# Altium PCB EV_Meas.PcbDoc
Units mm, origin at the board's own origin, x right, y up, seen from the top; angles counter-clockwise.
Board outline 85 x 150 mm, 2 copper layers (Top Layer, Bottom Layer); 79 components, 48 nets, 278 pads, 76 vias.
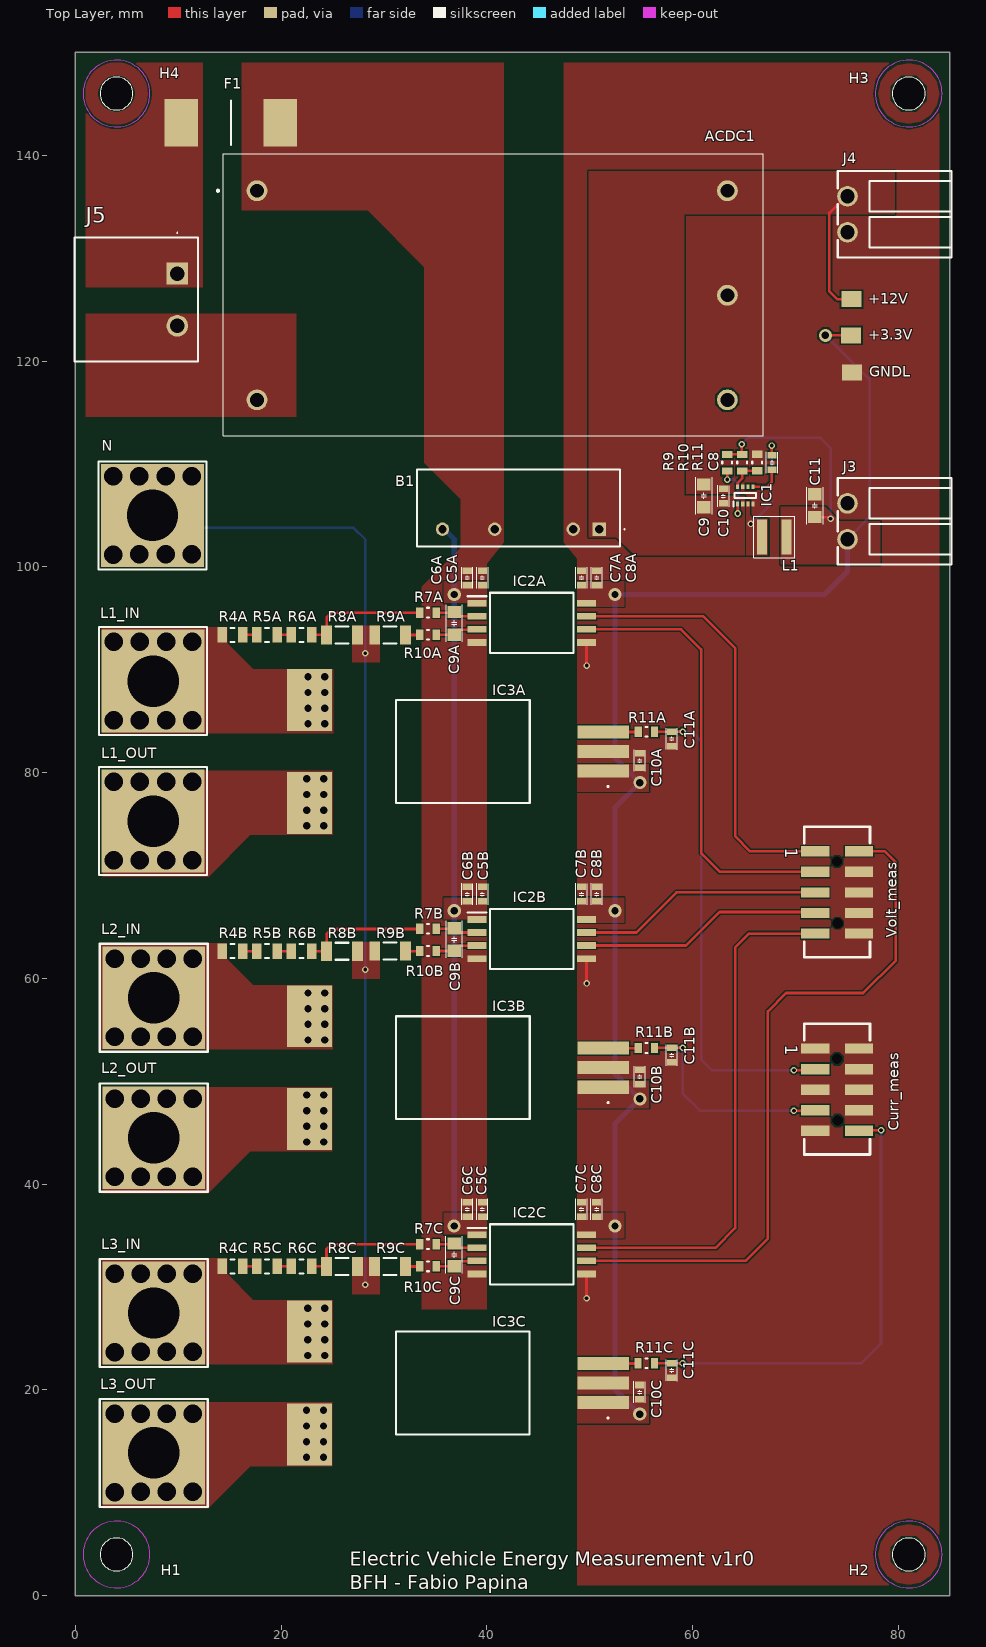
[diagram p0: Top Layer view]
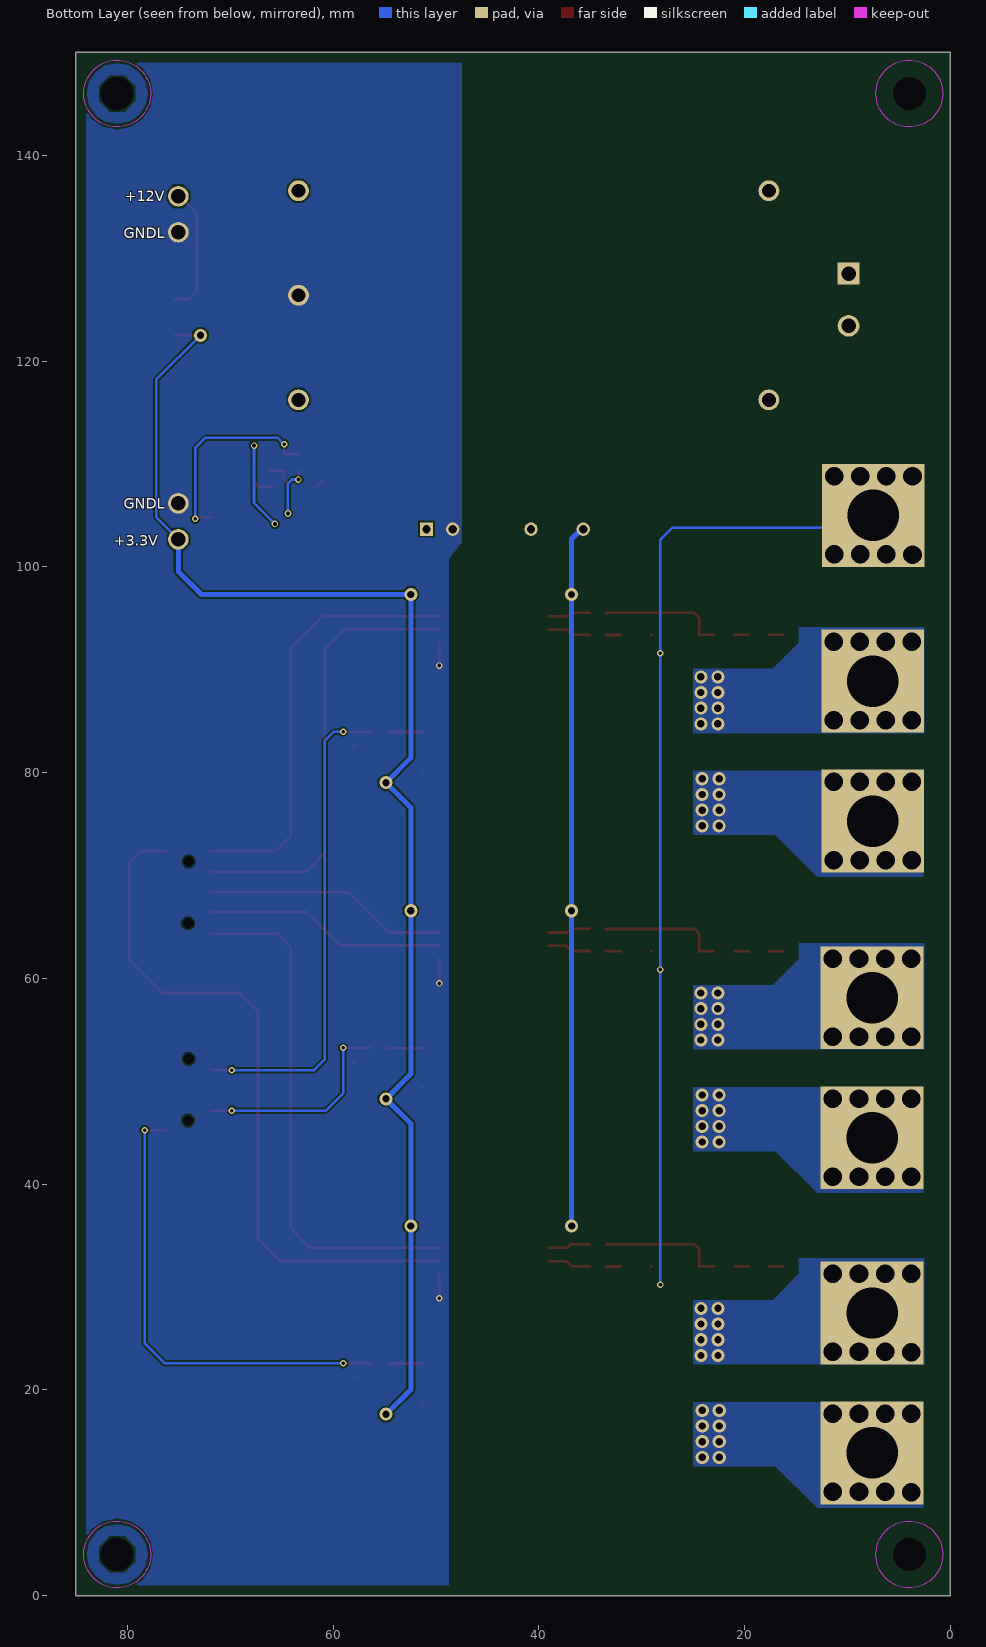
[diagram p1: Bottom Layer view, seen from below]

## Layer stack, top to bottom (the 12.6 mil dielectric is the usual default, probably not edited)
Top Solder: solder mask 0.0102, Solder Resist, Dk 3.5
Top Layer: signal copper 0.0356
Dielectric 1: dielectric 0.32, FR-4, Dk 4.8
Bottom Layer: signal copper 0.0356
Bottom Solder: solder mask 0.0102, Solder Resist, Dk 3.5

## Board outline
0,0 0,150 85,150 85,0

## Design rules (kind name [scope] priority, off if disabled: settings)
BoardOutlineClearance [All] p1: gap=1 ignorepadtopadclearanceinfootprint=FALSE
Clearance Clearance_multiCB [All] p1: gap=0.15 ignorepadtopadclearanceinfootprint=FALSE
Clearance [All] p2: gap=0.254 ignorepadtopadclearanceinfootprint=FALSE
Creepage [InNetClass('Isolated') vs InNetClass('Power')] p1: checkdistance=7
Height [All] p1: minheight=0 maxheight=60 prefheight=12.7
HoleSize HoleSize_multiCB [All] p1: absolutevalues=TRUE maxlimit=10 minlimit=0.2 maxpercent=80.000 minpercent=20.000
HoleSize [All] p2: absolutevalues=TRUE maxlimit=2.54 minlimit=0.025 maxpercent=80.000 minpercent=20.000
MinimumAnnularRing MinimumAnnularRing_multiCB [All] p1: minimumring=0.1
MinimumSolderMaskSliver MinimumSolderMaskSliver_multiCB [All] p1: minsoldermaskwidth=0.1
MinimumSolderMaskSliver [All] p2: minsoldermaskwidth=0.254
PlaneConnect [All] p1: planeconnectstyle=Direct reliefexpansion=0.508 reliefentries=4 reliefconductorwidth=0.254 reliefairgap=0.254
PolygonConnect PolygonConnect_Power [InNetClass('Power')] p1: connectstyle=Direct reliefconductorwidth=0.254 reliefentries=4 polygonreliefangle="90 Angle" airgapwidth=0.254
PolygonConnect [All] p2: connectstyle=Direct reliefconductorwidth=0.254 reliefentries=4 polygonreliefangle="90 Angle" airgapwidth=0.254
RoutingVias RoutingVias_multiCB [All] p1: holewidth=0.2 width=0.4 viastyle="Through Hole" minholewidth=0.2 minwidth=0.4 maxholewidth=0.2 maxwidth=0.4
RoutingVias [All] p2: holewidth=0.711 width=1.27 viastyle="Through Hole" minholewidth=0.711 minwidth=1.27 maxholewidth=0.711 maxwidth=1.27
SilkToSilkClearance SilkToSilkClearance_multiCB [All] p1: silktosilkclearance=0.1
SilkToSilkClearance [All] p2: silktosilkclearance=0.254
SilkToSolderMaskClearance SilkToSolderMaskClearance_multiCB [IsPad] p1: minsilkscreentomaskgap=0.15 clearancetoexposedcopper=TRUE
SilkToSolderMaskClearance [IsPad] p2: minsilkscreentomaskgap=0.254 clearancetoexposedcopper=TRUE
SolderMaskExpansion [All] p1: expansion=0.102 istentingtop=FALSE
Width High_current [InNetClass('High_Current')] p1: maxlimit=4.318 minlimit=0.254 preferedwidth=4.318 minimp=50.000000 maximp=50.000000 favimp=50.000000
Width Width_multiCB [All] p2: maxlimit=0.5 minlimit=0.254 preferedwidth=0.254
24 further rules are at their usual default settings.

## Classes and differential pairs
channel class Phase_Meas: U_Phase_Meas1 U_Phase_Meas2 U_Phase_Meas3
component class U_Phase_Meas3: C5C C6C C7C C8C C9C C10C C11C IC2C IC3C R4C R5C R6C R7C R8C R9C R10C R11C
component class U_Phase_Meas2: C5B C6B C7B C8B C9B C10B C11B IC2B IC3B R4B R5B R6B R7B R8B R9B R10B R11B
component class U_Phase_Meas1: C5A C6A C7A C8A C9A C10A C11A IC2A IC3A R4A R5A R6A R7A R8A R9A R10A R11A
component class TopSchematic: Curr_meas H1 H2 H3 H4 J3 J4 J5 L1_IN L1_OUT L2_IN L2_OUT L3_IN L3_OUT M1 M2 M3 M4 M5 M6 M7 M8 Meas_iso1 Meas_iso2 N Volt_meas
component class U_Power_supplies: ACDC1 B1 C8 C9 C10 C11 F1 IC1 L1 R9 R10 R11

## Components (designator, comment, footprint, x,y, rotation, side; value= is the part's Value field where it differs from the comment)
ACDC1 "RAC10-12SK_277" RAC1005SK277 17.653,136.548 r0 top
B1 "MDS01M-05N" MDS01M05N 50.927,103.655 r180 top
C5A "C-SMD-0603" C-0603 39.565,98.924 r270 top value=1uF (schematic designator C5)
C5B "C-SMD-0603" C-0603 39.565,68.19 r270 top value=1uF (schematic designator C5)
C5C "C-SMD-0603" C-0603 39.559,37.54 r270 top value=1uF (schematic designator C5)
C6A "C-SMD-0603" C-0603 38.091,98.924 r270 top value=0.1uF (schematic designator C6)
C6B "C-SMD-0603" C-0603 38.091,68.19 r270 top value=0.1uF (schematic designator C6)
C6C "C-SMD-0603" C-0603 38.085,37.54 r270 top value=0.1uF (schematic designator C6)
C7A "C-SMD-0603" C-0603 49.198,98.924 r270 top value=1uF (schematic designator C7)
C7B "C-SMD-0603" C-0603 49.198,68.19 r270 top value=1uF (schematic designator C7)
C7C "C-SMD-0603" C-0603 49.192,37.54 r270 top value=1uF (schematic designator C7)
C8 "C-SMD-0603" C-0603 67.725,110.132 r270 top value=0.1uF
C8A "C-SMD-0603" C-0603 50.674,98.924 r270 top value=0.1uF (schematic designator C8)
C8B "C-SMD-0603" C-0603 50.674,68.19 r270 top value=0.1uF (schematic designator C8)
C8C "C-SMD-0603" C-0603 50.668,37.54 r270 top value=0.1uF (schematic designator C8)
C9 "C-SMD-0805" C-0805 61.096,106.893 r270 top value=22uF
C9A "C-SMD-0805" C-0805 36.83,94.511 r90 top value=330pF (schematic designator C9)
C9B "C-SMD-0805" C-0805 36.83,63.777 r90 top value=330pF (schematic designator C9)
C9C "C-SMD-0805" C-0805 36.824,33.127 r90 top value=330pF (schematic designator C9)
C10 "C-SMD-0603" C-0603 62.993,106.868 r270 top value=0.1uF
C10A "C-SMD-0603" C-0603 54.853,81.158 r270 top value=0.1uF (schematic designator C10)
C10B "C-SMD-0603" C-0603 54.853,50.424 r270 top value=0.1uF (schematic designator C10)
C10C "C-SMD-0603" C-0603 54.847,19.774 r270 top value=0.1uF (schematic designator C10)
C11 "C-SMD-0805" C-0805 71.882,105.941 r270 top value=22uF
C11A "C-SMD-0603" C-0603 57.971,83.27 r90 top value=680nF (schematic designator C11)
C11B "C-SMD-0603" C-0603 57.971,52.536 r90 top value=680nF (schematic designator C11)
C11C "C-SMD-0603" C-0603 57.965,21.886 r90 top value=680nF (schematic designator C11)
Curr_meas "Molex MILLI-GRID SMD 5x2 2mm 87832-1020" 87832-1020r 74.041,49.172 r270 top
F1 "0465002.DR" FUSC12145X450N 15.113,143.152 r0 top
H1 "3.2" HOLE_3.2_NP 4,4 r0 top
H2 "3.2" HOLE_3.2_NP 81,4 r0 top
H3 "3.2" HOLE_3.2_NP 81,146 r0 top
H4 "3.2" HOLE_3.2_NP 4,146 r0 top
IC1 "TPS562211DRLR" SOTFL50P160X60-8N 65.123,106.938 r90 top
IC2A "AMC1300BDWV" SOIC127P1150X280-8N 44.361,94.555 r0 top (schematic designator IC2)
IC2B "AMC1300BDWV" SOIC127P1150X280-8N 44.361,63.821 r0 top (schematic designator IC2)
IC2C "AMC1300BDWV" SOIC127P1150X280-8N 44.355,33.17 r0 top (schematic designator IC2)
IC3A "ACS773KCB-150B-SMT-T" ACS772LCB050BSMTT 37.665,82.046 r90 top (schematic designator IC3)
IC3B "ACS773KCB-150B-SMT-T" ACS772LCB050BSMTT 37.665,51.312 r90 top (schematic designator IC3)
IC3C "ACS773KCB-150B-SMT-T" ACS772LCB050BSMTT 37.659,20.662 r90 top (schematic designator IC3)
J3 "Weidmuller_3.5 2X1" SL_3_50_90G_02 79.629,104.417 r90 top
J4 "Weidmuller_3.5 2X1" SL_3_50_90G_02 79.629,134.262 r90 top
J5 "1821140000" 1821140000 9.906,128.502 r270 top
L1 "XAL4030-472MEC" XAL4030472MEC 67.945,102.893 r0 top
L1_IN "Borne_4mm" Borne4mm_WE 7.553,88.881 r0 top
L1_OUT "Borne_4mm" Borne4mm_WE 7.553,75.275 r0 top
L2_IN "Borne_4mm" Borne4mm_WE 7.62,58.113 r0 top
L2_OUT "Borne_4mm" Borne4mm_WE 7.62,44.507 r0 top
L3_IN "Borne_4mm" Borne4mm_WE 7.62,27.472 r0 top
L3_OUT "Borne_4mm" Borne4mm_WE 7.62,13.866 r0 top
N "Borne_4mm" Borne4mm_WE 7.5,105 r0 top
R4A "R-SMD-0805" R-0805 15.285,93.383 r0 top value=2.2Meg (schematic designator R4)
R4B "R-SMD-0805" R-0805 15.285,62.649 r0 top value=2.2Meg (schematic designator R4)
R4C "R-SMD-0805" R-0805 15.279,31.999 r0 top value=2.2Meg (schematic designator R4)
R5A "R-SMD-0805" R-0805 18.642,93.383 r0 top value=2.2Meg (schematic designator R5)
R5B "R-SMD-0805" R-0805 18.642,62.649 r0 top value=2.2Meg (schematic designator R5)
R5C "R-SMD-0805" R-0805 18.636,31.999 r0 top value=2.2Meg (schematic designator R5)
R6A "R-SMD-0805" R-0805 22,93.383 r0 top value=2.2Meg (schematic designator R6)
R6B "R-SMD-0805" R-0805 22,62.649 r0 top value=2.2Meg (schematic designator R6)
R6C "R-SMD-0805" R-0805 21.994,31.999 r0 top value=2.2Meg (schematic designator R6)
R7A "R-SMD-0603" R-0603 34.29,95.527 r0 top value=12 (schematic designator R7)
R7B "R-SMD-0603" R-0603 34.29,64.793 r0 top value=12 (schematic designator R7)
R7C "R-SMD-0603" R-0603 34.284,34.143 r0 top value=12 (schematic designator R7)
R8A "R-SMD-1206" R-1206 25.908,93.368 r180 top value=5.62k (schematic designator R8)
R8B "R-SMD-1206" R-1206 25.908,62.634 r180 top value=5.62k (schematic designator R8)
R8C "R-SMD-1206" R-1206 25.902,31.984 r180 top value=5.62k (schematic designator R8)
R9 "R-SMD-0603" R-0603 63.373,110.132 r90 top value=10k
R9A "R-SMD-1206" R-1206 30.607,93.368 r0 top value=5.62k (schematic designator R9)
R9B "R-SMD-1206" R-1206 30.607,62.634 r0 top value=5.62k (schematic designator R9)
R9C "R-SMD-1206" R-1206 30.601,31.984 r0 top value=5.62k (schematic designator R9)
R10 "R-SMD-0603" R-0603 64.83,110.132 r90 top value=45.3k
R10A "R-SMD-0603" R-0603 34.29,93.368 r0 top value=12 (schematic designator R10)
R10B "R-SMD-0603" R-0603 34.29,62.634 r0 top value=12 (schematic designator R10)
R10C "R-SMD-0603" R-0603 34.284,31.984 r0 top value=12 (schematic designator R10)
R11 "R-SMD-0603" R-0603 66.25,110.132 r270 top value=10k
R11A "R-SMD-0603" R-0603 55.513,83.949 r0 top value=12 (schematic designator R11)
R11B "R-SMD-0603" R-0603 55.513,53.215 r0 top value=12 (schematic designator R11)
R11C "R-SMD-0603" R-0603 55.507,22.564 r0 top value=12 (schematic designator R11)
Volt_meas "Molex MILLI-GRID SMD 5x2 2mm 87832-1020" 87832-1020r 74.041,68.349 r270 top

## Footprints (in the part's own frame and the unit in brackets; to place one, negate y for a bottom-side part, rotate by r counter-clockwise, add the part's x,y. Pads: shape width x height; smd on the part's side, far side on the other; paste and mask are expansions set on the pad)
87832-1020r [mm]
  round 0 hole 1 unplated mask+0: 0(-3,0) 0(3,0.051)
  rect 1x2.75 smd: 1(-4,-2.125) 2(-4,2.125) 3(-2,-2.125) 4(-2,2.125) 5(0,-2.125) 6(0,2.125) 7(2,-2.125) 8(2,2.125) 9(4,-2.125) 10(4,2.125)
  silkscreen extent -6.4,-3.2 6.3,3.2, body extent -8.32,-3.15 8.33,3.15, height 15.15
1821140000 [mm]
  rect 2.1x2.1 hole 1.4: 1(0,0)
  round 2.1 hole 1.4: 2(5.08,0)
  silkscreen extent -4,-10 8.57,2, body extent -3.49,-10 8.57,2, height 8.21
ACS772LCB050BSMTT [mm]
  rect 1.27x5.03 smd: 1(-1.9,-13.655) 2(0,-13.655) 3(1.9,-13.655)
  rect 6.01x4.4 smd: 4(4.995,14.9) 5(-4.995,14.9)
  silkscreen extent -4.99,-14.17 5,6.5, body extent -7,-14.83 7,14.82, height 7.5
Borne4mm_WE [mm]
  rect 2x2 hole 1.8: 1(-3.81,-3.81) 1(-3.81,3.81) 1(-1.27,-3.785) 1(-1.27,3.81) 1(1.27,-3.785) 1(1.27,3.81) 1(3.81,-3.785) 1(3.81,3.81)
  round 6 hole 5: 1(0,0)
  rect 10x10 smd far side paste-5: 1(0,0)
  rect 10x10 smd paste-5: 1(0,0)
  silkscreen extent -5.25,-5.25 5.25,5.25, body extent -4.5,-4.5 4.5,4.5, height 7
C-0603 [mm]
  rect 0.64x0.89 smd mask+0.05: 1(-0.7,0) 2(0.7,0)
  silkscreen extent -1.05,-0.55 1.02,0.55, body extent -0.9,-0.5 0.9,0.5, height 1.4
C-0805 [mm]
  rect 1.2x1.3 smd: 1(-1.1,0) 2(1.1,0)
  silkscreen extent -1.8,-0.8 1.8,0.8, body extent -1,-0.62 1,0.63, height 0.6
FUSC12145X450N [mm]
  rect 3.26x4.61 smd: 1(-4.825,0) 2(4.825,0)
  silkscreen extent 0,-2.15 0,2.15, body extent -6.05,-2.25 6.05,2.25, height 4.5
HOLE_3.2_NP [mm] "Hole non plated"
  round 0 hole 3.2 unplated: 0(0,0)
  Keep-Out Layer circle w0.1: c0,0 r3.25
  silkscreen extent -1.6,-1.6 1.6,1.6
MDS01M05N [mm]
  rect 1.3x1.3 hole 0.8: 1(0,0)
  round 1.3 hole 0.8: 2(2.54,0) 5(10.16,0) 7(15.24,0)
  silkscreen extent -2.5,-5.8 17.7,1.7, body extent -2,-5.8 17.7,1.7, height 12.1
R-0603 [mm]
  rect 0.7x1 smd: 1(-0.809,0.019) 2(0.791,0.019)
  silkscreen extent -0.11,-0.46 0.09,0.49, body extent -0.88,-0.46 0.87,0.49, height 0.54
R-0805 [mm]
  rect 0.9x1.5 smd: 1(-1.009,0) 2(0.991,0)
  silkscreen extent -0.21,-0.68 0.19,0.68, body extent -1.11,-0.67 1.09,0.68, height 0.69
R-1206 [mm]
  rect 1.05x1.85 smd: 1(-1.515,0.003) 2(1.485,0.003)
  silkscreen extent -0.64,-0.82 0.61,0.83, body extent -1.64,-0.82 1.61,0.83, height 0.69
RAC1005SK277 [mm]
  round 2.025 hole 1.35: 1(0,0) 2(0,-20.32) 3(45.72,-20.32) 4(45.72,-10.16) 5(45.72,0)
  silkscreen extent -3.9,-23.82 49.2,3.58, body extent -3.26,-23.73 49.24,3.67, height 23.01
SL_3_50_90G_02 [mm]
  round 2 hole 1.4: A1(-1.75,4.58) A2(1.75,4.58)
  silkscreen extent -4.2,-5.53 4.2,5.53, body extent -4.2,-5.52 4.2,5.53, height 7.46
SOIC127P1150X280-8N [mm]
  rect 1.85x0.65 smd: 1(-5.325,1.905) 2(-5.325,0.635) 3(-5.325,-0.635) 4(-5.325,-1.905) 5(5.325,-1.905) 6(5.325,-0.635) 7(5.325,0.635) 8(5.325,1.905)
  silkscreen extent -6.25,-2.93 4.05,2.93, body extent -5.77,-2.93 5.77,2.93, height 2.7
SOTFL50P160X60-8N [mm]
  rect 0.475x0.3 smd: 1(-0.838,0.75) 2(-0.838,0.25) 3(-0.838,-0.25) 4(-0.838,-0.75) 5(0.838,-0.75) 6(0.838,-0.25) 7(0.838,0.25) 8(0.838,0.75)
  silkscreen extent -1.07,-1.05 0.25,1.15, body extent -0.8,-1.05 0.8,1.05, height 0.6
XAL4030472MEC [mm]
  rect 0.98x3.4 smd: 1(-1.185,0) 2(1.185,0)
  silkscreen extent -2,-2 2,2, body extent -2,-2 2,2, height 3.1

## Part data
ACDC1: "Power Supply", Arrow Part Number=RAC10-12SK/277, Manufacturer_Name="RECOM Power", Mouser Part Number=919-RAC10-12SK/277
B1: "Isolated DC/DC Converters - Through Hole 1W 12Vin 5Vout 20-200mA SIP7 Medical Unregulated", Manufacturer_Name="Mean Well"
C5A C5B C5C C6A C6B C6C C7A C7B C7C C8 C8A C8B C8C C10 C10A C10B C10C C11A C11B C11C: library part CMP-003-000008-1, "Multilayer Ceramic Capacitors MLCC", Manufacturer="Murata Electronics", Mfr. Part No.=GRM18..., Package=0603
C9 C11: library part CMP-001-00107-1, "Multilayer Ceramic Capacitors MLCC", Case/Package=0805, Manufacturer="Murata Electronics", Mfr. Part No.=GRM21*
C9A C9B C9C: library part CMP-003-000005-1, "Multilayer Ceramic Capacitors MLCC", Manufacturer="Murata Electronics", Mfr. Part No.=GRM21*, Package=0805
Curr_meas Volt_meas: "87832-1020 -  Connecteur fil-à-carte, 2 mm, 10 Contact(s), Embase, Milli-Grid 87832 Series, Montage CMS", Colour=Black, Manufacturer=Molex, Manufacturer P/N=87832-1020, Manufacturer Part Number=0878321014, Max Operating Temperature=105°C, Min Operating Temperature=-55°C, Package Quantity=500, Supplier Part Number 1=WM14376TR-ND
F1: "Fuse", Manufacturer_Name=LITTELFUSE, Mouser Part Number=576-0465002.DR
H1 H2 H3 H4: library part HOLE_3.2_NP, "Hole 3.2 unplated"
IC1: "Integrated Circuit", Manufacturer_Name="Texas Instruments", Mouser Part Number=595-TPS562211DRLR
IC2A IC2B IC2C: "Integrated Circuit", Manufacturer_Name="Texas Instruments", Mouser Part Number=595-AMC1300BDWV
IC3A IC3B IC3C: "Integrated Circuit", Manufacturer_Name="Allegro Microsystems", Mouser Part Number=250-773KCB150BSMTT
J3 J4: "Series BL/SL 3.50 2-Pin", Manufacturer=Weidmuller, Manufacturer P/N="SL 3.50/02/90G"
J5: "Connector", Manufacturer_Name=Weidmuller, Mouser Part Number=470-1821140000
L1: "Inductor", Manufacturer_Name=COILCRAFT, Mouser Part Number=994-XAL4030-472MEC
L1_IN L1_OUT L2_IN L2_OUT L3_IN L3_OUT N: library part Borne_4mm_WE, "Borne 4mm avec connecteur WE", Manufacturer=WE, Manufacturer P/N=7460305
R4A R4B R4C R5A R5B R5C R6A R6B R6C: library part CMP-013-000007-1, "Thin Film Resistors - SMD  0.1W  1%", Manufacturer="Vishay / Beyschlag", Mfr. Part No.=MCT06030C*, Package=0805
R7A R7B R7C R9 R10 R10A R10B R10C R11 R11A R11B R11C: library part CMP-013-000006-1, "Thin Film Resistors - SMD  0.1W  1%", Manufacturer="Vishay / Beyschlag", Mfr. Part No.=MCU08050C*, Package=0603
R8A R8B R8C R9A R9B R9C: library part CMP-013-000008-1, "Thin Film Resistors - SMD  0.1W  1%", Manufacturer="Vishay / Beyschlag", Mfr. Part No.=MCA12060C, Package=1206

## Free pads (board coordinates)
  rect 1.95x1.55 smd: TP(75.4,122.5) TP(75.438,126.007) TP(75.5,118.9)

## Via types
v1: diameter 1.27, hole 0.711, Top Layer to Bottom Layer, 58 vias
v2: diameter 0.635, hole 0.356, Top Layer to Bottom Layer, 18 vias

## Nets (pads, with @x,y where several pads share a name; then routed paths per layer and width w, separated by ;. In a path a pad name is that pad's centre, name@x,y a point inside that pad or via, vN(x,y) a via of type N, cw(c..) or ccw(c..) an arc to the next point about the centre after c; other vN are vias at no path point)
GND5: ACDC1.1 B1.5 C5A.1 C5B.1 C5C.1 C6A.1 C6B.1 C6C.1 F1.2 IC2A.4 IC2B.4 IC2C.4
GNDL: ACDC1.4 B1.2 C7A.1 C7B.1 C7C.1 C8A.1 C8B.1 C8C.1 C9.1 C10.1 C10A.1 C10B.1 C10C.1 C11.1 C11A.1 C11B.1 C11C.1 Curr_meas.1 Curr_meas.2 Curr_meas.4 Curr_meas.5 Curr_meas.6 Curr_meas.8 Curr_meas.9 IC1.4 IC1.7 IC2A.5 IC2B.5 IC2C.5 IC3A.2 IC3B.2 IC3C.2 J3.A2 J4.A1 pad.TP@75.5,118.9 R11.1 Volt_meas.4 Volt_meas.6 Volt_meas.8 Volt_meas.10 | length 8.2
  Top Layer w0.254: IC2C.5 49.68,28.92 49.7,28.9 49.691,28.891 v2(49.685,28.891) ; IC2B.5 49.686,59.514 v2(49.7,59.5) ; IC2A.5 49.686,90.414 v2(49.7,90.4) ; C11C.1@57.84,21.186 C11C.1 ; C11B.1@57.846,51.836 C11B.1 ; C11A.1@57.846,82.57 C11A.1 ; C9.1@61.096,108.295 C9.1@61.606,107.784
L1_IN: IC3A.4 L1_IN.1 R4A.1
  other v1: 22.606,84.732 24.257,84.732 22.606,86.256 24.257,86.256 22.606,87.78 24.257,87.78 22.606,89.304 24.257,89.304
L1_IN_P: ACDC1.2 J5.2
L1_OUT: IC3A.5 L1_OUT.1
  other v1: 22.479,74.826 24.13,74.826 22.479,76.35 24.13,76.35 22.479,77.874 24.13,77.874 22.479,79.398 24.13,79.398
L2_IN: IC3B.4 L2_IN.1 R4B.1
  other v1: 22.606,53.998 24.257,53.998 22.606,55.522 24.257,55.522 22.606,57.046 24.257,57.046 22.606,58.57 24.257,58.57
L2_OUT: IC3B.5 L2_OUT.1
  other v1: 22.479,44.092 24.13,44.092 22.479,45.616 24.13,45.616 22.479,47.14 24.13,47.14 22.479,48.664 24.13,48.664
L3_IN: IC3C.4 L3_IN.1 R4C.1
  other v1: 22.6,23.348 24.251,23.348 22.6,24.872 24.251,24.872 22.6,26.396 24.251,26.396 22.6,27.92 24.251,27.92
L3_OUT: IC3C.5 L3_OUT.1
  other v1: 22.473,13.442 24.124,13.442 22.473,14.966 24.124,14.966 22.473,16.49 24.124,16.49 22.473,18.014 24.124,18.014
MI1: C11A.2 Curr_meas.3 R11A.2 | length 47.4
  Top Layer w0.254: R11A.2 56.307,83.97 C11A.2 ; C11A.2@57.972,83.971 v2(59.027,83.972) v2(59.027,83.972) ; v2(69.85,51.077) 71.821,51.077 Curr_meas.3
  Bottom Layer w0.254: v2@59.039,83.961 v2(59.027,83.972) 59.942,83.972 60.833,83.081 60.833,52.093 61.849,51.077 v2(69.85,51.077)
MI2: C11B.2 Curr_meas.7 R11B.2 | length 20.8
  Top Layer w0.254: R11B.2 56.307,53.236 C11B.2 ; C11B.2@57.972,53.237 v2(59.027,53.238) v2(59.027,53.238) ; v2(69.85,47.14) 71.884,47.14 Curr_meas.7
  Bottom Layer w0.254: v2@59.039,53.227 v2(59.027,53.238) 59.027,48.819 60.706,47.14 v2(69.85,47.14)
MI3: C11C.2 Curr_meas.10 R11C.2 | length 45.7
  Top Layer w0.254: R11C.2 56.301,22.586 C11C.2 ; C11C.2@57.966,22.587 59.02,22.587 v2(59.021,22.588) ; Curr_meas.10 76.229,45.235 v2(78.312,45.235)
  Bottom Layer w0.254: v2(59.021,22.588) 76.413,22.588 78.312,24.487 v2(78.312,45.235)
MVN1: IC2A.6 Volt_meas.3 | length 43.6
  Top Layer w0.254: IC2A.6 58.884,93.92 60.833,91.971 60.833,72.159 62.643,70.349 Volt_meas.3
MVN2: IC2B.6 Volt_meas.7 | length 23.6
  Top Layer w0.254: IC2B.6 59.353,63.186 62.611,66.444 71.821,66.444 Volt_meas.7
MVN3: IC2C.6 Volt_meas.2 | length 68.7
  Top Layer w0.254: IC2C.6 65.151,32.535 67.31,34.694 67.31,56.792 69.088,58.57 76.581,58.57 79.756,61.745 79.756,71.27 78.677,72.349 Volt_meas.2
MVP1: IC2A.7 Volt_meas.1 | length 42.4
  Top Layer w0.254: IC2A.7 61.043,95.19 64.135,92.098 64.135,73.81 65.596,72.349 Volt_meas.1
MVP2: IC2B.7 Volt_meas.5 | length 23.8
  Top Layer w0.254: IC2B.7 54.527,64.456 58.42,68.349 Volt_meas.5
MVP3: IC2C.7 Volt_meas.9 | length 50.9
  Top Layer w0.254: IC2C.7 62.23,33.805 64.135,35.71 64.135,63.015 65.469,64.349 Volt_meas.9
N: N.1 R8A.1 R8B.1 R8C.1 R9A.1 R9B.1 R9C.1 | length 94.5
  Top Layer w0.254: R9C.1@29.081,31.981 R9C.1 ; R9B.1@29.087,62.631 R9B.1 ; R9A.1@29.087,93.365 R9A.1
  Bottom Layer w0.254: N.1@7.553,106.068 8.562,106.068 10.848,103.782 27.051,103.782 28.194,102.639 v2(28.194,60.856) v2@28.197,60.859 ; v2(28.188,30.206) 28.191,30.209 v2@28.191,60.853 ; v2(28.194,91.59) v2@28.197,91.593
N_P: F1.1 J5.1
NetC8_1: C8.1 IC1.3 L1.1 | length 9.5
  Top Layer w0.254: v2(65.659,104.163) v2@65.659,104.266 ; v2(67.691,111.783) 67.691,110.866 C8.1
  Bottom Layer w0.254: v2(65.659,104.163) 67.691,106.195 v2(67.691,111.783)
NetC8_2: C8.2 IC1.5 | length 3.2
  Top Layer w0.254: IC1.5 67.24,107.776 67.691,108.227 67.691,109.398 C8.2
NetC9A_1: C9A.1 IC2A.3 R10A.2 | length 5.5
  Top Layer w0.254: R10A.2 36.806,93.387 C9A.1@37.303,93.884 ; IC2A.3 39,93.884 C9A.1@37.303,93.884 ; C9A.1@37.303,93.884 C9A.1 C9A.1@37.303,93.884
NetC9A_2: C9A.2 IC2A.2 R7A.2 | length 4.2
  Top Layer w0.254: R7A.2 36.765,95.546 C9A.2 37.252,95.189 IC2A.2
NetC9B_1: C9B.1 IC2B.3 R10B.2 | length 5.5
  Top Layer w0.254: R10B.2 36.806,62.653 C9B.1@37.303,63.15 ; IC2B.3 39,63.15 C9B.1@37.303,63.15 ; C9B.1@37.303,63.15 C9B.1 C9B.1@37.303,63.15
NetC9B_2: C9B.2 IC2B.2 R7B.2 | length 4.2
  Top Layer w0.254: R7B.2 36.765,64.812 C9B.2 37.252,64.455 IC2B.2
NetC9C_1: C9C.1 IC2C.3 R10C.2 | length 5.5
  Top Layer w0.254: R10C.2 36.8,32.003 C9C.1@37.297,32.5 ; IC2C.3 38.994,32.5 C9C.1@37.297,32.5 ; C9C.1@37.297,32.5 C9C.1 C9C.1@37.297,32.5
NetC9C_2: C9C.2 IC2C.2 R7C.2 | length 4.2
  Top Layer w0.254: R7C.2 36.759,34.162 C9C.2 C9C.2@37.246,33.805 ; C9C.2@37.246,33.805 IC2C.2
NetIC1_1: IC1.1 R9.1 | length 5.9
  Top Layer w0.254: R9.1 63.373,109.304 v2(63.373,108.481) ; IC1.1 64.381,106.092 64.381,105.187 v2(64.389,105.179) v2@64.395,105.185
  Bottom Layer w0.254: v2(63.373,108.481) 64.008,108.481 64.406,108.083 64.406,105.196 v2(64.389,105.179)
NetIC1_8: IC1.8 R10.1 R11.2 | length 3.2
  Top Layer w0.254: IC1.8 64.396,107.799 64.396,108.177 64.811,108.592 R10.1 ; R10.1@64.82,109.332 66.26,109.332 R11.2
NetIC3A_3: IC3A.3 R11A.1 | length 3.4
  Top Layer w0.254: IC3A.3 54.683,83.946 R11A.1
NetIC3B_3: IC3B.3 R11B.1 | length 3.4
  Top Layer w0.254: IC3B.3 54.683,53.212 R11B.1
NetIC3C_3: IC3C.3 R11C.1 | length 3.4
  Top Layer w0.254: IC3C.3 54.677,22.562 R11C.1
NetR4A_2: R4A.2 R5A.1 | length 1.4
  Top Layer w0.254: R4A.2 R5A.1
NetR4B_2: R4B.2 R5B.1 | length 1.4
  Top Layer w0.254: R4B.2 R5B.1
NetR4C_2: R4C.2 R5C.1 | length 1.4
  Top Layer w0.254: R4C.2 R5C.1
NetR5A_2: R5A.2 R6A.1 | length 1.4
  Top Layer w0.254: R5A.2 R6A.1
NetR5B_2: R5B.2 R6B.1 | length 1.4
  Top Layer w0.254: R5B.2 R6B.1
NetR5C_2: R5C.2 R6C.1 | length 1.4
  Top Layer w0.254: R5C.2 R6C.1
NetR6A_2: R6A.2 R7A.1 R8A.2 | length 12.4
  Top Layer w0.254: R6A.2 24.405,93.383 R8A.2 24.423,95.058 24.892,95.527 33.45,95.527 R7A.1@33.481,95.496
NetR6B_2: R6B.2 R7B.1 R8B.2 | length 12.4
  Top Layer w0.254: R6B.2 24.405,62.649 R8B.2 24.423,64.324 24.892,64.793 33.45,64.793 R7B.1@33.481,64.762
NetR6C_2: R6C.2 R7C.1 R8C.2 | length 12.4
  Top Layer w0.254: R6C.2 24.399,31.999 R8C.2 24.417,33.674 24.886,34.143 33.444,34.143 R7C.1@33.475,34.112
NetR9A_2: R9A.2 R10A.1 | length 1.4
  Top Layer w0.254: R9A.2 33.465,93.371 R10A.1
NetR9B_2: R9B.2 R10B.1 | length 1.4
  Top Layer w0.254: R9B.2 33.465,62.637 R10B.1
NetR9C_2: R9C.2 R10C.1 | length 1.4
  Top Layer w0.254: R9C.2 33.459,31.986 R10C.1
VCC3_3: C7A.2 C7B.2 C7C.2 C8A.2 C8B.2 C8C.2 C10A.2 C10B.2 C10C.2 C11.2 IC2A.8 IC2B.8 IC2C.8 IC3A.1 IC3B.1 IC3C.1 J3.A1 L1.2 pad.TP@75.4,122.5 R9.2 R10.2 | length 156.6
  Top Layer w0.254: IC3C.1 IC3C.1@51.321,18.769 ; IC3B.1 IC3B.1@51.327,49.419 ; IC3A.1 IC3A.1@51.327,80.153 ; R9.2 R10.2 64.77,110.965 v2(64.77,111.91) ; C11.2 71.925,104.798 73.176,104.798 73.303,104.671 v2(73.406,104.671) ; v1(72.9,122.5) pad.TP@75.4,122.5
  Bottom Layer w0.254: v2(64.77,111.91) 65.405,112.545 72.39,112.545 73.406,111.529 v2(73.406,104.671) ; v1(72.9,122.5) 77.2,118.2 77.2,104.818 J3.A1
  Bottom Layer w0.5: v1(54.858,17.633) 52.445,20.046 v1(52.445,35.921) 52.445,45.864 v1(54.864,48.283) 52.451,50.696 v1(52.451,66.571) 52.451,76.604 v1(54.864,79.017) 52.451,81.43 v1(52.451,97.305) 72.805,97.305 75.049,99.549 J3.A1
VCC5: B1.7 C5A.2 C5B.2 C5C.2 C6A.2 C6B.2 C6C.2 IC2A.1 IC2B.1 IC2C.1 | length 68.3
  Bottom Layer w0.254: B1.7 B1.7@35.867,103.655 ; v1(36.824,35.921) v1@36.827,35.924 ; v1(36.83,66.571) v1@36.833,66.574 ; v1(36.83,97.305) v1@36.833,97.308
  Bottom Layer w0.5: B1.7@35.867,103.655 36.83,102.692 v1(36.83,66.571) ; v1@36.827,35.924 v1@36.827,66.568
VCC12: ACDC1.5 B1.1 C9.2 C10.2 IC1.2 J4.A2 pad.TP@75.438,126.007 | length 12.5
  Top Layer w0.254: J4.A2 74.902,136.012 73.279,134.389 73.279,126.769 74.041,126.007 pad.TP@75.438,126.007
pads on no net: ACDC1.3 Curr_meas.0 H1.0 H2.0 H3.0 H4.0 IC1.6 Volt_meas.0

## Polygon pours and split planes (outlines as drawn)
GNDL on Top Layer "GNDL_L01_P151" (solid, pour order 151): 85,0 48.768,0 48.768,100.765 47.488,102.368 47.488,150 85,150
GND5 on Top Layer "GND5_L01_P150" (solid, pour order 150): 33.655,98.05 37.465,101.86 37.465,106.576 33.933,110.108 33.933,129.132 28.43,134.636 37.465,134.636 16.192,134.636 16.192,150 41.656,150 41.656,102.385 40.005,100.282 40.005,27.836 33.655,27.836
L1_IN_P on Top Layer "L1_IN_P_L01_P149" (solid, pour order 149): 21.463,124.61 -0.254,124.61 -0.254,114.577 2.54,114.577 21.463,114.577
L3_OUT on Top Layer "L3_OUT_L01_P147" (solid, pour order 147): 2.642,18.802 24.994,18.802 24.994,12.579 16.993,12.579 12.929,8.515 2.642,8.515
L2_OUT on Top Layer "L2_OUT_L01_P145" (solid, pour order 145): 2.642,49.409 24.994,49.409 24.994,43.186 16.993,43.186 12.929,39.122 2.642,39.122
L1_IN on Top Layer "L1_IN_L01_P144" (solid, pour order 144): 25.051,83.825 2.572,83.825 2.572,94.112 14.764,94.112 14.764,92.588 17.304,90.048 25.051,90.048
L2_IN on Top Layer "L2_IN_L01_P142" (solid, pour order 142): 25.017,53.126 2.538,53.126 2.538,63.413 14.73,63.413 14.73,61.889 17.27,59.349 25.017,59.349
L3_IN on Top Layer "L3_IN_L01_P141" (solid, pour order 141): 25.037,22.5 2.558,22.5 2.558,32.787 14.75,32.787 14.75,31.263 17.29,28.723 25.037,28.723
L1_OUT on Top Layer "L1_OUT_L01_P140" (solid, pour order 140): 2.667,80.16 25.019,80.16 25.019,73.937 17.018,73.937 12.954,69.873 2.667,69.873
VCC3_3 on Top Layer "VCC3_3_L01_P139" (solid, pour order 139): 48.768,80.795 48.768,78.128 55.753,78.128 55.753,80.795
VCC3_3 on Top Layer "VCC3_3_L01_P138" (solid, pour order 138): 48.768,50.061 48.768,47.394 55.753,47.394 55.753,50.061
VCC3_3 on Top Layer "VCC3_3_L01_P137" (solid, pour order 137): 48.762,19.411 48.762,16.744 55.747,16.744 55.747,19.411
N on Top Layer "N_L01_P136" (solid, pour order 136): 26.924,94.257 29.591,94.257 29.591,90.701 26.924,90.701
N on Top Layer "N_L01_P135" (solid, pour order 135): 26.924,63.523 29.591,63.523 29.591,59.967 26.924,59.967
N on Top Layer "N_L01_P134" (solid, pour order 134): 26.918,32.873 29.585,32.873 29.585,29.317 26.918,29.317
VCC3_3 on Top Layer "VCC3_3_L01_P133" (solid, pour order 133): 48.763,96.137 48.763,98.575 53.346,98.575 53.346,96.137
VCC3_3 on Top Layer "VCC3_3_L01_P132" (solid, pour order 132): 48.763,65.403 48.763,67.841 53.346,67.841 53.346,65.403
VCC3_3 on Top Layer "VCC3_3_L01_P131" (solid, pour order 131): 48.757,34.753 48.757,37.191 53.34,37.191 53.34,34.753
VCC5 on Top Layer "VCC5_L01_P130" (solid, pour order 130): 40.011,98.575 40.011,96.124 38.106,96.124 38.106,96.491 35.814,96.491 35.814,98.575
VCC5 on Top Layer "VCC5_L01_P129" (solid, pour order 129): 40.011,67.841 40.011,65.39 38.106,65.39 38.106,65.757 35.814,65.757 35.814,67.841
VCC5 on Top Layer "VCC5_L01_P128" (solid, pour order 128): 40.005,37.191 40.005,34.74 38.1,34.74 38.1,35.107 35.808,35.107 35.808,37.191
N_P on Top Layer "N_P_L01_P127" (solid, pour order 127): -0.212,150 12.361,150 12.361,127.15 -0.212,127.15 -0.212,145.311
VCC12 on Top Layer "VCC12_L01_P126" (solid, pour order 126): 60.434,106.888 65.043,106.888 65.043,101.115 54.364,101.115 52.586,102.893 49.911,102.893 49.911,138.453 79.629,138.453 79.629,134.262 59.182,134.262 59.182,106.888
VCC3_3 on Top Layer "VCC3_3_L01_P125" (solid, pour order 125): 68.58,100.226 78.232,100.226 78.232,104.417 74.295,104.417 72.898,105.814 68.58,105.814 68.58,104.163
NetC8_1 on Top Layer "NETC8_1_L01_P124" (solid, pour order 124): 65.532,106.379 65.532,105.052 65.913,104.671 67.31,104.671 67.31,101.115 65.225,101.115 65.225,106.379
GNDL on Bottom Layer "GNDL_L02_P156" (solid, pour order 156): 85,0 48.768,0 48.768,100.765 47.488,102.368 47.488,150 85,150
L1_OUT on Bottom Layer "L1_OUT_L02_P154" (solid, pour order 154): 2.667,80.16 25.019,80.16 25.019,73.937 17.018,73.937 12.954,69.873 2.667,69.873
L2_OUT on Bottom Layer "L2_OUT_L02_P153" (solid, pour order 153): 2.667,49.426 25.019,49.426 25.019,43.203 17.018,43.203 12.954,39.139 2.667,39.139
L3_OUT on Bottom Layer "L3_OUT_L02_P152" (solid, pour order 152): 2.667,18.819 25.019,18.819 25.019,12.596 17.018,12.596 12.954,8.532 2.667,8.532
L1_IN on Bottom Layer "L1_IN_L02_P148" (solid, pour order 148): 25.019,83.843 2.54,83.843 2.54,94.13 14.732,94.13 14.732,92.606 17.272,90.066 25.019,90.066
L2_IN on Bottom Layer "L2_IN_L02_P146" (solid, pour order 146): 25.019,53.109 2.54,53.109 2.54,63.396 14.732,63.396 14.732,61.872 17.272,59.332 25.019,59.332
L3_IN on Bottom Layer "L3_IN_L02_P143" (solid, pour order 143): 25.019,22.502 2.54,22.502 2.54,32.789 14.732,32.789 14.732,31.265 17.272,28.725 25.019,28.725

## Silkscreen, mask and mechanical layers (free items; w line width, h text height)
Top Overlay:
  text "+12V" at 77.054,125.554 h1.02
  text "+3.3V" at 77.054,122.054 h1.02
  text "GNDL" at 77.154,118.454 h1.02
  text "Electric Vehicle Energy Measurement v1r0 / BFH - Fabio Papina" at 26.661,0.199 h2.29
Bottom Overlay:
  text "+12V" at 80.246,135.554 h1.02
  text "GNDL" at 80.346,131.954 h1.02
  text "GNDL" at 80.346,105.654 h1.02
  text "+3.3V" at 81.346,102.054 h1.02
Mechanical 1:
  the board outline again, w0.254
